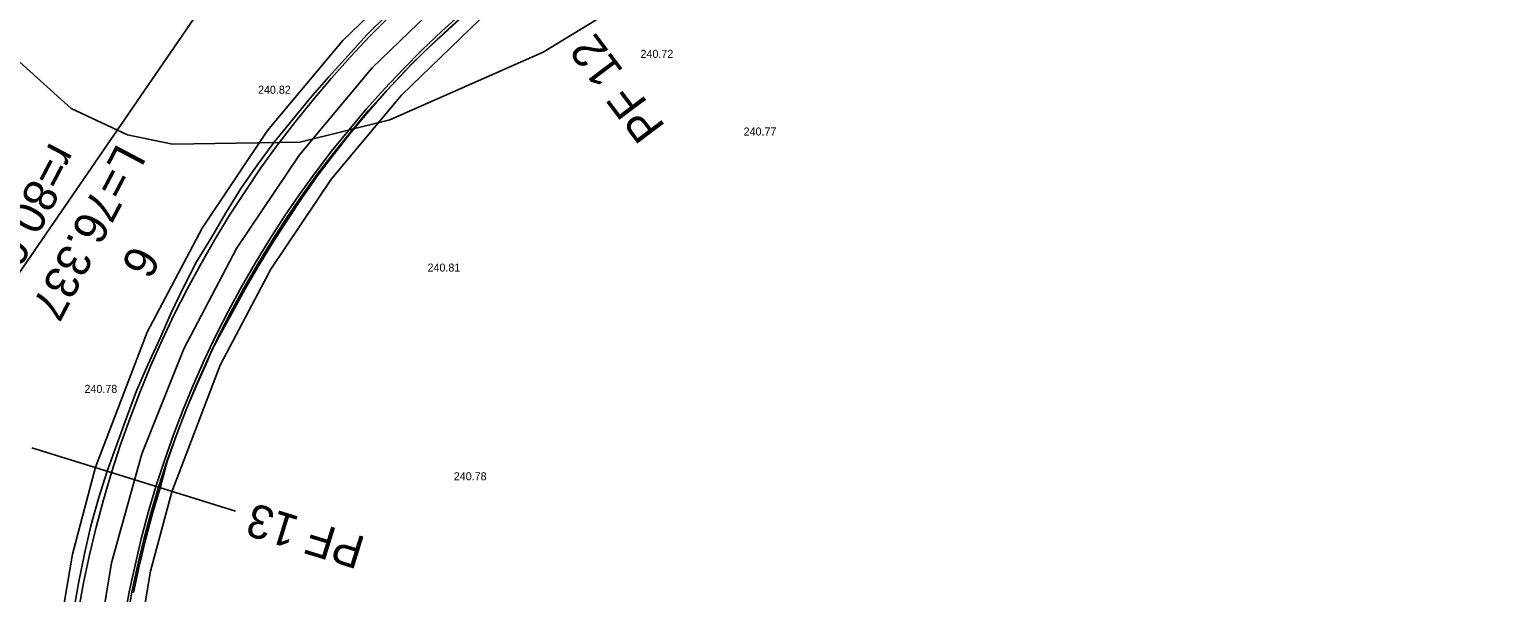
# Model space of a CAD drawing. Extents: x -555887 to -552101, y -1100251 to -1096546.
# Drawn here: x -555264.6 to -555153.8, y -1098074.8 to -1098032.6 of the extents above; entities that cross this region are included whole.
import ezdxf

# ---------------------------------------------------------------- set-up
doc = ezdxf.new("R2010")
doc.units = 0
for name, color, linetype in [('IP_návrh', 7, 'Continuous'), ('PARCELY_cesty', 7, 'Continuous'), ('POLYGONY_SITUACE_PF', 7, 'Continuous'), ('POLYGONY_SITUACE_PF_POPISY', 7, 'Continuous'), ('POLYGONY_SITUACE_PO', 7, 'Continuous'), ('vrstevnice', 7, 'Continuous'), ('Výškopis', 7, 'Continuous')]:
    doc.layers.add(name, color=color, linetype=linetype)

msp = doc.modelspace()

# ---------------------------------------------------------------- linework, layer by layer
at = {"layer": 'IP_návrh'}
msp.add_lwpolyline([(-555730.85, -1098494.64), (-555471.29, -1098211.98), (-555447.19, -1098191.79), (-555406.99, -1098193.78), (-555291.32, -1098130.27), (-555281.27, -1098119.66), (-555272.34, -1098101.41), (-555266.18, -1098052.11), (-555246.83, -1098023.92), (-555193.03, -1097978.41), (-554985.79, -1097744.7), (-554956.17, -1097701), (-554939.23, -1097656.04), (-554918.86, -1097601.97), (-554899.16, -1097585.1)], dxfattribs=at)
at = {"layer": 'PARCELY_cesty'}
for points in [[(-555160.11, -1097954.47), (-555192.77, -1097992.48), (-555199.51, -1097999.69), (-555209.27, -1098008.52), (-555217.12, -1098014.5), (-555227.87, -1098021.99), (-555234.74, -1098027.35), (-555241.07, -1098033.46), (-555246.71, -1098040.2), (-555251.61, -1098047.51), (-555255.72, -1098055.31), (-555259.6, -1098065.43), (-555261.34, -1098071.96), (-555262.8, -1098080.63), (-555263.34, -1098092.85), (-555263.89, -1098100.4), (-555265.39, -1098107.66), (-555267.81, -1098114.66), (-555271.12, -1098121.29), (-555275.26, -1098127.43), (-555280.16, -1098132.99), (-555285.74, -1098137.86), (-555292.25, -1098142.16), (-555364.66, -1098183.69)], [(-555155.6, -1097958.43), (-555188.3, -1097996.49), (-555195.3, -1098003.98), (-555205.43, -1098013.14), (-555213.59, -1098019.35), (-555224.3, -1098026.82), (-555230.8, -1098031.88), (-555236.67, -1098037.55), (-555241.91, -1098043.81), (-555246.45, -1098050.59), (-555250.25, -1098057.79), (-555253.88, -1098067.28), (-555255.47, -1098073.23), (-555256.82, -1098081.27), (-555257.35, -1098093.21), (-555257.94, -1098101.22), (-555259.59, -1098109.25), (-555262.26, -1098116.99), (-555265.92, -1098124.32), (-555270.5, -1098131.11), (-555275.93, -1098137.25), (-555282.1, -1098142.64), (-555289.09, -1098147.26), (-555393.06, -1098207.11)]]:
    msp.add_lwpolyline(points, dxfattribs=at)
at = {"layer": 'POLYGONY_SITUACE_PF'}
for p, q in [((-555256.74, -1098066.35), (-555264.38, -1098063.98)), ((-555249.1, -1098068.72), (-555256.74, -1098066.35))]:
    msp.add_line(p, q, dxfattribs=at)
at = {"layer": 'POLYGONY_SITUACE_PO'}
for p, q in [((-555232.77, -1098029.62), (-555238.87, -1098035.51)), ((-555237.72, -1098031.49), (-555239.24, -1098032.99)), ((-555237.56, -1098031.66), (-555239.06, -1098033.16)), ((-555232.12, -1098031.38), (-555233.63, -1098032.75)), ((-555231.99, -1098031.53), (-555233.5, -1098032.9)), ((-555231.97, -1098031.56), (-555233.47, -1098032.92)), ((-555239.24, -1098032.99), (-555240.67, -1098034.58)), ((-555239.06, -1098033.16), (-555240.52, -1098034.71)), ((-555233.63, -1098032.75), (-555235.11, -1098034.16)), ((-555233.5, -1098032.9), (-555234.97, -1098034.3)), ((-555233.47, -1098032.92), (-555234.96, -1098034.31)), ((-555235.11, -1098034.16), (-555236.55, -1098035.6)), ((-555234.97, -1098034.3), (-555236.41, -1098035.74)), ((-555234.96, -1098034.31), (-555235.98, -1098035.31)), ((-555238.87, -1098035.51), (-555244.31, -1098042.01)), ((-555240.67, -1098034.58), (-555242.1, -1098036.16)), ((-555240.52, -1098034.71), (-555241.94, -1098036.3)), ((-555236.55, -1098035.6), (-555237.94, -1098037.08)), ((-555235.98, -1098035.31), (-555236.4, -1098035.74)), ((-555242.1, -1098036.16), (-555243.52, -1098037.76)), ((-555241.94, -1098036.3), (-555243.31, -1098037.93)), ((-555236.41, -1098035.74), (-555237.8, -1098037.22)), ((-555236.4, -1098035.74), (-555237.78, -1098037.23)), ((-555243.52, -1098037.76), (-555244.87, -1098039.41)), ((-555237.94, -1098037.08), (-555239.3, -1098038.6)), ((-555237.8, -1098037.22), (-555239.15, -1098038.73)), ((-555237.78, -1098037.23), (-555239.13, -1098038.76)), ((-555243.31, -1098037.93), (-555244.65, -1098039.59)), ((-555239.3, -1098038.6), (-555240.62, -1098040.16)), ((-555239.15, -1098038.73), (-555240.46, -1098040.29)), ((-555239.13, -1098038.76), (-555240.43, -1098040.32)), ((-555244.87, -1098039.41), (-555246.2, -1098041.08)), ((-555244.65, -1098039.59), (-555245.95, -1098041.27)), ((-555246.2, -1098041.08), (-555247.48, -1098042.79)), ((-555240.62, -1098040.16), (-555241.9, -1098041.74)), ((-555240.46, -1098040.29), (-555241.74, -1098041.87)), ((-555240.43, -1098040.32), (-555241.69, -1098041.91)), ((-555244.31, -1098042.01), (-555249.03, -1098049.05)), ((-555245.95, -1098041.27), (-555247.2, -1098043)), ((-555241.9, -1098041.74), (-555243.14, -1098043.36)), ((-555241.74, -1098041.87), (-555242.98, -1098043.48)), ((-555241.69, -1098041.91), (-555242.91, -1098043.53)), ((-555247.48, -1098042.79), (-555248.7, -1098044.55)), ((-555247.2, -1098043), (-555248.39, -1098044.76)), ((-555243.14, -1098043.36), (-555244.33, -1098045.01)), ((-555242.98, -1098043.48), (-555244.17, -1098045.12)), ((-555242.91, -1098043.53), (-555244.08, -1098045.19)), ((-555248.7, -1098044.55), (-555249.84, -1098046.36)), ((-555248.39, -1098044.76), (-555249.55, -1098046.55)), ((-555244.33, -1098045.01), (-555245.48, -1098046.69)), ((-555244.17, -1098045.12), (-555245.31, -1098046.8)), ((-555244.08, -1098045.19), (-555245.2, -1098046.88)), ((-555249.84, -1098046.36), (-555250.92, -1098048.21)), ((-555249.55, -1098046.55), (-555250.65, -1098048.36)), ((-555245.48, -1098046.69), (-555246.58, -1098048.41)), ((-555245.31, -1098046.8), (-555246.41, -1098048.51)), ((-555245.2, -1098046.88), (-555246.3, -1098048.58)), ((-555250.92, -1098048.21), (-555252.03, -1098050.04)), ((-555250.65, -1098048.36), (-555251.72, -1098050.21)), ((-555246.58, -1098048.41), (-555247.64, -1098050.15)), ((-555246.41, -1098048.51), (-555247.47, -1098050.25)), ((-555246.3, -1098048.58), (-555247.36, -1098050.31)), ((-555252.03, -1098050.04), (-555253, -1098051.94)), ((-555249.03, -1098049.05), (-555252.98, -1098056.55)), ((-555251.72, -1098050.21), (-555252.73, -1098052.08)), ((-555247.64, -1098050.15), (-555248.66, -1098051.91)), ((-555247.47, -1098050.25), (-555248.49, -1098052.01)), ((-555247.36, -1098050.31), (-555248.38, -1098052.07)), ((-555253, -1098051.94), (-555253.93, -1098053.86)), ((-555252.73, -1098052.08), (-555253.7, -1098053.98)), ((-555248.66, -1098051.91), (-555249.63, -1098053.7)), ((-555248.49, -1098052.01), (-555249.46, -1098053.8)), ((-555248.38, -1098052.07), (-555249.35, -1098053.85)), ((-555253.93, -1098053.86), (-555254.79, -1098055.82)), ((-555253.7, -1098053.98), (-555254.61, -1098055.9)), ((-555249.63, -1098053.7), (-555250.56, -1098055.52)), ((-555249.46, -1098053.8), (-555250.38, -1098055.61)), ((-555249.35, -1098053.85), (-555250.34, -1098055.63)), ((-555250.56, -1098055.52), (-555251.43, -1098057.36)), ((-555252.98, -1098056.55), (-555256.12, -1098064.43)), ((-555254.79, -1098055.82), (-555255.68, -1098057.76)), ((-555254.61, -1098055.9), (-555255.47, -1098057.85)), ((-555250.38, -1098055.61), (-555251.24, -1098057.45)), ((-555250.34, -1098055.63), (-555250.9, -1098056.72)), ((-555255.68, -1098057.76), (-555256.52, -1098059.72)), ((-555251.43, -1098057.36), (-555252.25, -1098059.23)), ((-555251.24, -1098057.45), (-555252.07, -1098059.3)), ((-555251.22, -1098057.46), (-555252.04, -1098059.32)), ((-555250.9, -1098056.72), (-555251.22, -1098057.46)), ((-555255.47, -1098057.85), (-555256.28, -1098059.82)), ((-555256.52, -1098059.72), (-555257.27, -1098061.72)), ((-555256.28, -1098059.82), (-555257.04, -1098061.8)), ((-555252.25, -1098059.23), (-555253.03, -1098061.11)), ((-555252.07, -1098059.3), (-555252.84, -1098061.18)), ((-555252.04, -1098059.32), (-555252.66, -1098060.75)), ((-555253.03, -1098061.11), (-555253.76, -1098063.01)), ((-555252.66, -1098060.75), (-555252.83, -1098061.19)), ((-555257.27, -1098061.72), (-555258.01, -1098063.72)), ((-555257.04, -1098061.8), (-555257.75, -1098063.81)), ((-555252.84, -1098061.18), (-555253.57, -1098063.08)), ((-555252.83, -1098061.19), (-555253.55, -1098063.09)), ((-555253.76, -1098063.01), (-555254.44, -1098064.93)), ((-555253.57, -1098063.08), (-555254.25, -1098065)), ((-555253.55, -1098063.09), (-555254.22, -1098065.01)), ((-555258.01, -1098063.72), (-555258.73, -1098065.74)), ((-555257.75, -1098063.81), (-555258.41, -1098065.83)), ((-555256.12, -1098064.43), (-555258.4, -1098072.59)), ((-555254.44, -1098064.93), (-555255.07, -1098066.87)), ((-555254.25, -1098065), (-555254.88, -1098066.93)), ((-555254.22, -1098065.01), (-555254.76, -1098066.97)), ((-555258.73, -1098065.74), (-555259.39, -1098067.77)), ((-555258.41, -1098065.83), (-555259.01, -1098067.88)), ((-555259.39, -1098067.77), (-555259.96, -1098069.83)), ((-555255.07, -1098066.87), (-555255.65, -1098068.82)), ((-555254.88, -1098066.93), (-555255.45, -1098068.88)), ((-555254.76, -1098066.97), (-555255.33, -1098068.91)), ((-555259.01, -1098067.88), (-555259.56, -1098069.93)), ((-555255.65, -1098068.82), (-555256.17, -1098070.79)), ((-555255.45, -1098068.88), (-555255.98, -1098070.84)), ((-555259.96, -1098069.83), (-555260.44, -1098071.92)), ((-555259.56, -1098069.93), (-555260.06, -1098072)), ((-555255.33, -1098068.91), (-555255.85, -1098070.87)), ((-555256.17, -1098070.79), (-555256.64, -1098072.78)), ((-555255.98, -1098070.84), (-555256.45, -1098072.82)), ((-555255.85, -1098070.87), (-555256.32, -1098072.85)), ((-555260.44, -1098071.92), (-555260.86, -1098074.01)), ((-555260.06, -1098072), (-555260.5, -1098074.09)), ((-555258.4, -1098072.59), (-555259.81, -1098080.95)), ((-555256.64, -1098072.78), (-555257.07, -1098074.77)), ((-555256.45, -1098072.82), (-555256.87, -1098074.81)), ((-555256.32, -1098072.85), (-555256.75, -1098074.83)), ((-555260.86, -1098074.01), (-555261.22, -1098076.12)), ((-555260.5, -1098074.09), (-555260.89, -1098076.18)), ((-555257.07, -1098074.77), (-555257.44, -1098076.77)), ((-555256.87, -1098074.81), (-555257.24, -1098076.81))]:
    msp.add_line(p, q, dxfattribs=at)
at = {"layer": 'vrstevnice'}
msp.add_lwpolyline([(-555291.05, -1097952.89), (-555284.73, -1097963.99), (-555280.8, -1097974.1), (-555278.41, -1097983.08), (-555273.22, -1098022.26), (-555268.16, -1098032.51), (-555261.42, -1098038.55), (-555257.21, -1098040.51), (-555253.84, -1098041.21), (-555244.29, -1098041.07), (-555237.55, -1098039.39), (-555226.04, -1098034.33), (-555214.8, -1098027.45), (-555197.95, -1098013.41), (-555168.18, -1097982.8), (-555142.35, -1097959.63)], dxfattribs=at)

# ---------------------------------------------------------------- texts
for s, p in [('r=80.0', (-555262.99, -1098040.97)), ('L=76.337', (-555257.96, -1098041.07)), ('6', (-555256.86, -1098048.65))]:
    msp.add_text(s, height=2.5, rotation=242.2266).set_placement(p)
at = {"layer": 'POLYGONY_SITUACE_PF_POPISY'}
for s, rotation, p in [('PF 12', 126.9784, (-555216.82, -1098039.89)), ('PF 13', 162.7882, (-555239.25, -1098070.72))]:
    msp.add_text(s, height=2.5, rotation=rotation, dxfattribs=at).set_placement(p)
at = {"layer": 'Výškopis'}
for s, p in [('240.72', (-555218.74, -1098034.75)), ('240.82', (-555247.42, -1098037.44)), ('240.77', (-555211.01, -1098040.57)), ('240.81', (-555234.71, -1098050.77)), ('240.78', (-555260.43, -1098059.86)), ('240.78', (-555232.74, -1098066.41))]:
    msp.add_text(s, height=0.6, dxfattribs=at).set_placement(p)

doc.saveas('drawing.dxf')
